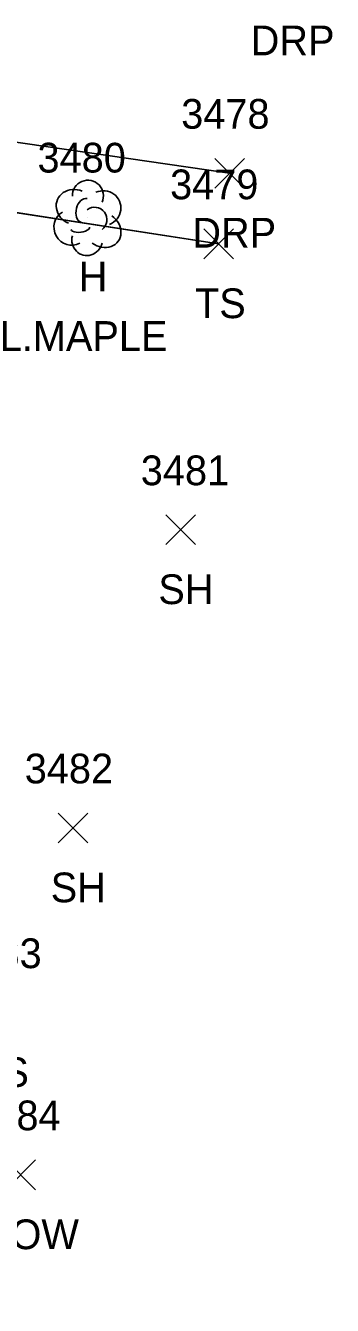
# Model space of a CAD drawing. Extents: x 1554668 to 1563881, y 831386 to 834374.
# Drawn here: x 1562477.8 to 1562498.5, y 833496.6 to 833582.7 of the extents above; entities that cross this region are included whole.
import ezdxf

# ---------------------------------------------------------------- set-up
doc = ezdxf.new("R2010")
doc.units = 0
for name, color, linetype in [('L_A', 7, 'Continuous'), ('L_C', 7, 'Continuous'), ('L_I', 7, 'Continuous'), ('L_TIC', 7, 'Continuous'), ('LELB', 7, 'Continuous'), ('LTD', 7, 'Continuous'), ('R_A', 7, 'Continuous'), ('R_I', 7, 'Continuous'), ('R_TIC', 7, 'Continuous'), ('RDP', 7, 'Continuous')]:
    doc.layers.add(name, color=color, linetype=linetype)

msp = doc.modelspace()

# ---------------------------------------------------------------- linework, layer by layer
at = {"layer": 'L_TIC'}
for points in [[(1562489.813, 833567.031), (1562491.813, 833569.031)], [(1562491.813, 833567.031), (1562489.813, 833569.031)], [(1562487.266, 833547.79), (1562489.266, 833549.79)], [(1562489.266, 833547.79), (1562487.266, 833549.79)], [(1562480.016, 833527.727), (1562482.016, 833529.727)], [(1562482.016, 833527.727), (1562480.016, 833529.727)], [(1562476.482, 833504.387), (1562478.482, 833506.387)], [(1562478.482, 833504.387), (1562476.482, 833506.387)]]:
    msp.add_lwpolyline(points, dxfattribs=at)
at = {"layer": 'LELB'}
for points in [[(1562437.583, 833496.603), (1562429.547, 833499.845), (1562434.14, 833516.438), (1562439.282, 833532.692), (1562438.525, 833538.257), (1562443.165, 833563.786), (1562457.076, 833572.086), (1562468.754, 833571.429), (1562490.813, 833568.031)], [(1562437.579, 833496.606), (1562429.548, 833499.85), (1562434.142, 833516.444), (1562439.278, 833532.693), (1562438.522, 833538.259), (1562443.166, 833563.788), (1562457.078, 833572.088), (1562468.756, 833571.43), (1562490.814, 833568.038)], [(1562437.579, 833496.606), (1562429.548, 833499.85), (1562434.142, 833516.444), (1562439.278, 833532.693), (1562438.522, 833538.259), (1562443.166, 833563.788), (1562457.078, 833572.088), (1562468.756, 833571.43), (1562490.814, 833568.038)], [(1562437.579, 833496.606), (1562429.548, 833499.85), (1562434.142, 833516.444), (1562439.278, 833532.693), (1562438.522, 833538.259), (1562443.166, 833563.788), (1562457.078, 833572.088), (1562468.756, 833571.43), (1562490.814, 833568.038)]]:
    msp.add_lwpolyline(points, dxfattribs=at)
at = {"layer": 'LTD'}
msp.add_line((1562481.961, 833569.829), (1562481.961, 833569.829), dxfattribs=at)
msp.add_line((1562481.961, 833569.829), (1562481.961, 833569.829), dxfattribs=at)
msp.add_arc((1562482.008, 833571.263), 1.047, 335.52715, 180.95627, dxfattribs=at)
for centre, major_axis, ratio, start_param, end_param in [((1562481.17, 833570.496), (1.21, -0.512), 0.895232, 1.570796, 4.712389), ((1562483.003, 833570.413), (-1.141, -0.483), 0.949671, 1.570796, 4.712389), ((1562481.753, 833570.287), (-0.208, -0.792), 0.645439, 3.141593, 6.283185), ((1562480.878, 833569.121), (0.584, -1.042), 0.959034, 3.141593, 6.283185), ((1562482.461, 833569.663), (-0.5, 0.667), 0.989748, 3.141593, 6.283185), ((1562482.961, 833568.996), (-1.09, 0.792), 0.841452, 1.570796, 4.712389), ((1562481.503, 833569.079), (-0.625, -0.083), 0.423636, 0, 3.141593), ((1562481.962, 833568.329), (0.265, 1.061), 0.942809, 1.570796, 4.712389)]:
    msp.add_ellipse(centre, major_axis=major_axis, ratio=ratio, start_param=start_param, end_param=end_param, dxfattribs=at)
at = {"layer": 'R_TIC'}
for points in [[(1562490.554, 833571.777), (1562492.554, 833573.777)], [(1562492.554, 833571.777), (1562490.554, 833573.777)]]:
    msp.add_lwpolyline(points, dxfattribs=at)
at = {"layer": 'RDP'}
for points in [[(1562424.853, 833574.142), (1562432.113, 833577.256), (1562444.622, 833578.953), (1562456.864, 833578.902), (1562468.178, 833576.176), (1562491.555, 833572.783)], [(1562424.853, 833574.142), (1562432.113, 833577.256), (1562444.622, 833578.953), (1562456.864, 833578.902), (1562468.178, 833576.176), (1562491.555, 833572.783)], [(1562424.853, 833574.142), (1562432.113, 833577.256), (1562444.622, 833578.953), (1562456.864, 833578.902), (1562468.178, 833576.176), (1562491.555, 833572.783)], [(1562424.854, 833574.14), (1562432.113, 833577.255), (1562444.621, 833578.943), (1562456.863, 833578.901), (1562468.176, 833576.173), (1562491.554, 833572.777)]]:
    msp.add_lwpolyline(points, dxfattribs=at)

# ---------------------------------------------------------------- texts
at = {"layer": 'L_A'}
for s, p in [('H', (1562481.394, 833564.829)), ('TS', (1562489.223, 833563.031)), ('SH', (1562486.754, 833543.79)), ('SH', (1562479.504, 833523.727)), ('TS', (1562474.615, 833511.296)), ('HOW', (1562474.867, 833500.387))]:
    msp.add_text(s, height=2, dxfattribs=at).set_placement(p)
at = {"layer": 'L_C'}
msp.add_text('L.MAPLE', height=2, dxfattribs=at).set_placement((1562476.072, 833560.829))
at = {"layer": 'L_I'}
for s, p in [('3480', (1562478.615, 833572.829)), ('3479', (1562487.546, 833571.031)), ('3481', (1562485.573, 833551.79)), ('3482', (1562477.756, 833531.727)), ('3483', (1562472.946, 833519.296)), ('3484', (1562474.222, 833508.387))]:
    msp.add_text(s, height=2, dxfattribs=at).set_placement(p)
at = {"layer": 'R_A'}
for p in [(1562492.974, 833580.715), (1562489.043, 833567.777)]:
    msp.add_text('DRP', height=2, dxfattribs=at).set_placement(p)
at = {"layer": 'R_I'}
msp.add_text('3478', height=2, dxfattribs=at).set_placement((1562488.295, 833575.777))

doc.saveas('drawing.dxf')
